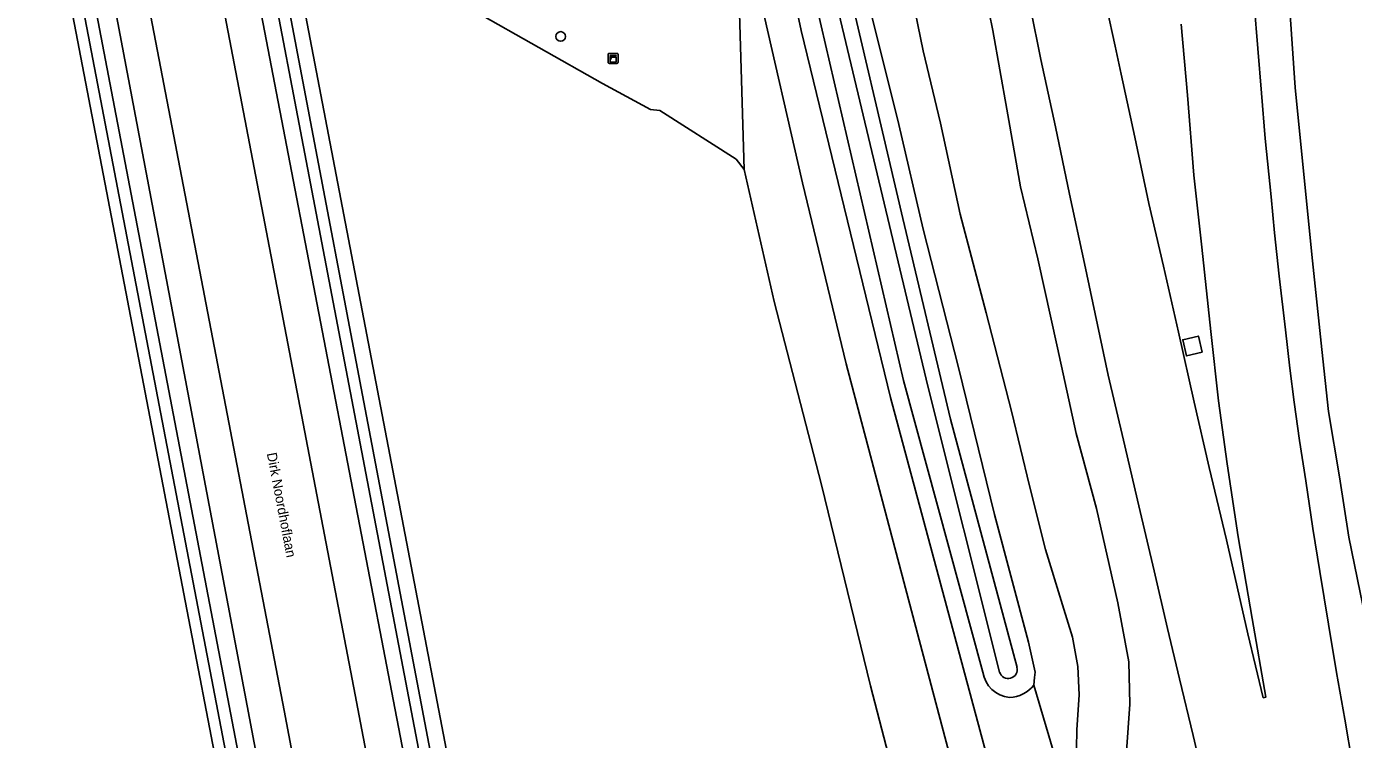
# Model space of a CAD drawing. Extents: x 155209 to 156748, y 385356 to 388487.
# Drawn here: x 155983.7 to 156118, y 387161.6 to 387233.8 of the extents above; entities that cross this region are included whole.
import ezdxf

# ---------------------------------------------------------------- set-up
doc = ezdxf.new("R2010")
doc.units = 0
for name, color, linetype in [('IMGEO_Berm_groen', 7, 'Continuous'), ('IMGEO_Boom', 7, 'Continuous'), ('IMGEO_Bouwland', 7, 'Continuous'), ('IMGEO_Grasland_overig', 7, 'Continuous'), ('IMGEO_Groenvoorziening', 7, 'Continuous'), ('IMGEO_Kast', 7, 'Continuous'), ('IMGEO_Oever', 7, 'Continuous'), ('IMGEO_Openbare_ruimte_label', 7, 'Continuous'), ('IMGEO_Rijbaan_autoweg', 7, 'Continuous'), ('IMGEO_Rijbaan_lokaal_gesloten', 7, 'Continuous'), ('IMGEO_Terreindeel_gesloten', 7, 'Continuous'), ('IMGEO_Waterloop', 7, 'Continuous')]:
    doc.layers.add(name, color=color, linetype=linetype)

msp = doc.modelspace()

# ---------------------------------------------------------------- linework, layer by layer
at = {"layer": 'IMGEO_Berm_groen'}
for points in [[(156124.08, 387145.73), (156119.4, 387172.12), (156119.79, 387171.29), (156118.68, 387176.53), (156117.56, 387182.12), (156116.6, 387188.23), (156115.48, 387194.83), (156114.83, 387201.12), (156113.86, 387210.09), (156112.91, 387219.48), (156112.12, 387227.62), (156111.58, 387235.49), (156111.1, 387240.26), (156110.59, 387248.51), (156110.09, 387261.29), (156109.74, 387274.5), (156109.48, 387287.23), (156109.39, 387301.2), (156109.43, 387313.84), (156109.38, 387326.21)], [(155947.88, 387283.75), (155948.71, 387282.8), (155982.58, 387264.03), (155982.51, 387264.23), (155983.11, 387265.71), (155985.52, 387266.24), (155987.41, 387263.41), (156023.19, 387074.38), (156023.15, 387072.76), (156022.07, 387071.71), (156020.54, 387071.32), (156012.96, 387067.09), (156012.12, 387066.35), (156011.18, 387065.51), (156010.73, 387065.11), (156010.1, 387065.36), (156008.59, 387064.11), (156010.29, 387063.34)], [(156025.74, 387080.22), (156009.76, 387164.56), (155992.17, 387256.24), (155990.17, 387266.67), (155989.94, 387268.35), (155987.99, 387269.6), (155983.87, 387268.2), (155983.02, 387267.92), (155974.17, 387271.92), (155969.49, 387274.19)], [(156080.41, 387238.88), (156081.52, 387233.39), (156082.94, 387225.44), (156084.32, 387217.55), (156086.06, 387210.27), (156088.06, 387201.26), (156089.96, 387192.59), (156092.02, 387185.03), (156094.18, 387175.46), (156095.27, 387169.51), (156095.39, 387165.23), (156095.04, 387160.42)], [(156107.97, 387236.09), (156108.7, 387227.03), (156109.08, 387222.45), (156109.7, 387216.55), (156110.03, 387212.91), (156110.51, 387208.51), (156111.14, 387203.11), (156111.58, 387199.2), (156112.01, 387195.76), (156112.54, 387191.91), (156113.18, 387187.81), (156113.92, 387182.98), (156114.61, 387178.63), (156115.49, 387173.3), (156116.31, 387168.41), (156117.14, 387163.7), (156117.92, 387159.1)], [(156103.18, 387156.15), (156101.8, 387162.04), (156100.4, 387167.78), (156099.19, 387172.87), (156097.83, 387178.72), (156096.29, 387185.27), (156094.75, 387191.94), (156093.18, 387198.52), (156090.8, 387209.8), (156089.28, 387216.83), (156087.85, 387223.62), (156086.37, 387230.44), (156085.32, 387235.63)], [(156093.06, 387235.66), (156093.89, 387231.81), (156094.5, 387228.98), (156095.88, 387222.59), (156097.31, 387215.88), (156098.79, 387209.53), (156100.32, 387202.86), (156101.88, 387195.79), (156103.4, 387189.18), (156105.15, 387181.86), (156107.32, 387172.34), (156108.89, 387165.86), (156109.16, 387165.93), (156107.77, 387173.87), (156106.35, 387182.15), (156105.24, 387189.55), (156104.36, 387195.91), (156103.59, 387202.91), (156102.67, 387211.47), (156101.86, 387218.76), (156101.22, 387226.85), (156100.59, 387234.04)]]:
    msp.add_lwpolyline(points, dxfattribs=at)
msp.add_lwpolyline([(156102.7, 387200.83), (156101.1, 387200.46), (156100.73, 387202.09), (156102.33, 387202.46)], close=True, dxfattribs=at)
at = {"layer": 'IMGEO_Boom'}
msp.add_circle((156037.77, 387232.78), 0.489, dxfattribs=at)
at = {"layer": 'IMGEO_Bouwland'}
for points in [[(155983.31, 387261.26), (155977.7, 387264.44), (155946.02, 387282), (155934.44, 387274.3), (155908.63, 387250), (155876.05, 387219.32), (155872.95, 387216.32), (155866.82, 387210.39), (155866.68, 387210.25), (155829.99, 387175.53), (155824.39, 387170.24), (155820.32, 387166.38), (155820.46, 387166.24), (155817.28, 387163.02), (155817.14, 387163.16), (155808.2, 387155.21), (155805.58, 387152.26), (155802.15, 387149.1), (155805.27, 387147.74), (155854.95, 387128.34), (156000, 387072.11), (156012.96, 387067.09), (156020.54, 387071.32), (156019.65, 387072.07)], [(156064.17, 387187.41), (156059.38, 387205.95), (156056.35, 387219.32), (156055.53, 387220.36), (156047.8, 387225.28), (156046.85, 387225.4), (156041.99, 387228.01), (156009.77, 387246.27), (156039.37, 387091.89), (156076.78, 387127.01), (156078.96, 387129.05), (156077.06, 387135.76), (156072.99, 387152.28), (156069.14, 387167.07)]]:
    msp.add_lwpolyline(points, close=True, dxfattribs=at)
msp.add_lwpolyline([(156044.88, 387040.73), (156001.43, 387266.35), (156001.45, 387267.92), (156002.48, 387269.35), (156004.33, 387269.73), (156005.47, 387268.66), (156009.77, 387246.27), (156041.99, 387228.01), (156046.85, 387225.4), (156047.8, 387225.28), (156055.53, 387220.36), (156056.35, 387219.32), (156055.84, 387236.29), (156047.02, 387279.97), (156046.87, 387280.78), (155998.24, 387271.2), (155998.01, 387270.89), (155997.11, 387269.67), (156016.95, 387166.15), (156032.7, 387083.72)], dxfattribs=at)
at = {"layer": 'IMGEO_Grasland_overig'}
for points in [[(156027.54, 387557.22), (156027.62, 387546.78), (156027.42, 387516.8), (156028.65, 387483.23), (156030.14, 387455.45), (156032.35, 387424.76), (156034.61, 387401.66), (156038.15, 387370.39), (156042.46, 387338.51), (156047.03, 387310.12), (156049.29, 387296.42), (156055.09, 387266.23), (156062.12, 387233.38), (156071.16, 387196.26), (156081.89, 387156.33), (156090.36, 387124.96), (156100.47, 387087.38), (156109.71, 387056.23), (156112.76, 387045.81), (156117.12, 387031.93)], [(156051.56, 387326.11), (156053.06, 387317.03), (156055.2, 387305.56), (156057.16, 387294.73), (156059.48, 387283.2), (156061.25, 387272.56), (156062.57, 387265.36), (156064.64, 387255.74), (156066.86, 387244.97), (156068.39, 387238.38), (156071.98, 387223.87), (156074.47, 387213.29), (156078.03, 387199.27), (156081.69, 387184.41), (156085.12, 387171.5), (156085.79, 387168.45), (156085.73, 387167.9), (156085.66, 387167.13), (156095.73, 387133.19)], [(156056.92, 387322), (156059.1, 387309.12), (156061.83, 387294.35), (156064.33, 387280.36), (156066.57, 387267.88), (156067, 387265.48), (156070.1, 387251.29), (156073.33, 387236.78), (156074.47, 387231.32), (156076.2, 387224.02), (156078.22, 387214.79), (156080.83, 387204.83), (156083.39, 387194.86), (156085.22, 387187.3), (156086.83, 387180.87), (156088.55, 387175.26), (156089.57, 387171.99), (156090.13, 387169.04), (156090.26, 387166.15), (156090, 387162.62), (156089.96, 387158.83)], [(156089.96, 387158.83), (156090, 387162.62), (156090.26, 387166.15), (156090.13, 387169.04), (156089.57, 387171.99), (156088.55, 387175.26), (156086.83, 387180.87), (156085.22, 387187.3), (156083.39, 387194.86), (156080.83, 387204.83), (156078.22, 387214.79), (156076.2, 387224.02), (156074.47, 387231.32), (156073.33, 387236.78), (156070.1, 387251.29), (156067, 387265.48), (156066.57, 387267.88), (156064.33, 387280.36), (156061.83, 387294.35), (156059.1, 387309.12), (156056.92, 387322)], [(156080.49, 387168.45), (156072.47, 387197.97), (156062.39, 387241.43), (156058.9, 387257.1), (156054.08, 387282.98), (156050.84, 387302.29), (156047.64, 387320.03)], [(156095.04, 387160.42), (156095.39, 387165.23), (156095.27, 387169.51), (156094.18, 387175.46), (156092.02, 387185.03), (156089.96, 387192.59), (156088.06, 387201.26), (156086.06, 387210.27), (156084.32, 387217.55), (156082.94, 387225.44), (156081.52, 387233.39), (156080.41, 387238.88)], [(156095.73, 387133.19), (156085.66, 387167.13)]]:
    msp.add_lwpolyline(points, dxfattribs=at)
for centre, radius, start, end in [((156083.5, 387168.93), 3.04, 189.1217, 264.4738), ((156083.09, 387169.19), 3.29, 272.035, 321.3376)]:
    msp.add_arc(centre, radius, start, end, dxfattribs=at)
at = {"layer": 'IMGEO_Groenvoorziening'}
msp.add_lwpolyline([(156109.38, 387326.21), (156109.43, 387313.84), (156109.39, 387301.2), (156109.48, 387287.23), (156109.74, 387274.5), (156110.09, 387261.29), (156110.59, 387248.51), (156111.1, 387240.26), (156111.58, 387235.49), (156112.12, 387227.62), (156112.91, 387219.48), (156113.86, 387210.09), (156114.83, 387201.12), (156115.48, 387194.83), (156116.6, 387188.23), (156117.56, 387182.12), (156118.68, 387176.53), (156119.79, 387171.29), (156120.29, 387168.65), (156121.38, 387164.83), (156122.51, 387161.99), (156123.57, 387158.75)], dxfattribs=at)
msp.add_lwpolyline([(156066.68, 387199.67), (156062.24, 387217.98), (156057.95, 387236.69), (156053.47, 387257.31), (156049.77, 387275.85), (156048.78, 387281.15), (156046.87, 387280.78), (156047.02, 387279.97), (156055.84, 387236.29), (156056.35, 387219.32), (156059.38, 387205.95), (156064.17, 387187.41), (156069.14, 387167.07), (156072.99, 387152.28), (156077.06, 387135.76), (156078.96, 387129.05), (156084.15, 387133.91), (156076.64, 387161.91)], close=True, dxfattribs=at)
at = {"layer": 'IMGEO_Kast'}
for p, q in [((156042.57, 387230.14), (156042.57, 387230.98)), ((156042.57, 387230.98), (156042.57, 387230.14)), ((156042.65, 387231.06), (156043.49, 387231.06)), ((156043.49, 387231.06), (156042.65, 387231.06)), ((156043.57, 387230.99), (156043.57, 387230.15)), ((156043.57, 387230.15), (156043.57, 387230.99)), ((156043.5, 387230.06), (156042.66, 387230.06)), ((156042.66, 387230.06), (156043.5, 387230.06))]:
    msp.add_line(p, q, dxfattribs=at)
for points in [[(156042.77, 387230.85), (156043.37, 387230.85), (156043.37, 387230.77), (156042.77, 387230.77), (156042.77, 387230.85)], [(156042.77, 387230.68), (156043.37, 387230.68), (156043.37, 387230.19), (156042.77, 387230.19), (156042.77, 387230.68)]]:
    msp.add_lwpolyline(points, dxfattribs=at)
msp.add_circle((156042.85, 387230.53), 0.0377, dxfattribs=at)
for centre, start, end in [((156042.65, 387230.99), 92.4484, 184.2845), ((156042.65, 387230.99), 92.4484, 184.2845), ((156043.49, 387230.99), 2.4484, 94.2845), ((156043.49, 387230.99), 2.4484, 94.2845), ((156042.65, 387230.14), 182.4484, 274.2845), ((156042.65, 387230.14), 182.4484, 274.2845), ((156043.49, 387230.14), 272.4484, 4.2845), ((156043.49, 387230.14), 272.4484, 4.2845)]:
    msp.add_arc(centre, 0.0779, start, end, dxfattribs=at)
at = {"layer": 'IMGEO_Oever'}
for points in [[(156047.63, 387341.22), (156051.29, 387316.99), (156055.64, 387291.24), (156060.36, 387267.05), (156065.95, 387241.84), (156072.4, 387214.36), (156077.24, 387194.04), (156083.96, 387168.94)], [(156082.2, 387168.45), (156074.93, 387197.4), (156064.5, 387241.1), (156055.96, 387282.33), (156052.8, 387300.61), (156047.25, 387331.74)], [(156085.66, 387167.13), (156085.73, 387167.9), (156085.79, 387168.45), (156085.12, 387171.5), (156081.69, 387184.41), (156078.03, 387199.27), (156074.47, 387213.29), (156071.98, 387223.87), (156068.39, 387238.38), (156066.86, 387244.97), (156064.64, 387255.74), (156062.57, 387265.36), (156061.25, 387272.56), (156059.48, 387283.2), (156057.16, 387294.73), (156055.2, 387305.56), (156053.06, 387317.03), (156051.56, 387326.11)], [(156047.64, 387320.03), (156050.84, 387302.29), (156054.08, 387282.98), (156058.9, 387257.1), (156062.39, 387241.43), (156072.47, 387197.97), (156080.49, 387168.45)]]:
    msp.add_lwpolyline(points, dxfattribs=at)
for points in [[(156001.43, 387266.35), (156044.88, 387040.73), (156045.6, 387038.35), (156046.7, 387037.25), (156048.01, 387037.48), (156049.03, 387038.45), (156049.4, 387039.61), (156040.62, 387085.43), (156039.37, 387091.89), (156009.77, 387246.27), (156005.47, 387268.66), (156004.33, 387269.73), (156002.48, 387269.35), (156001.45, 387267.92)], [(156002.8, 387268.42), (156002.71, 387268.82), (156003.86, 387269.09), (156004.03, 387268.32), (156047.43, 387040.3), (156046.43, 387040.12)], [(155982.58, 387264.03), (155983, 387262.89), (155983.31, 387261.26), (156019.65, 387072.07), (156020.54, 387071.32), (156022.07, 387071.71), (156023.15, 387072.76), (156023.19, 387074.38), (155987.41, 387263.41), (155985.52, 387266.24), (155983.11, 387265.71), (155982.51, 387264.23)], [(155984.17, 387263.08), (155983.89, 387264.11), (155984.17, 387264.17), (155983.98, 387265.13), (155984.9, 387265.42), (155985.06, 387264.36), (155985.28, 387263.86), (156021.93, 387072.6), (156022.03, 387072.16), (156020.84, 387071.88), (156020.71, 387072.48)]]:
    msp.add_lwpolyline(points, close=True, dxfattribs=at)
for centre, radius, start, end in [((156083.07, 387168.73), 0.912, 197.6383, 13.7261), ((156083.5, 387168.93), 3.04, 189.1217, 264.4738), ((156083.09, 387169.19), 3.29, 272.035, 321.3376)]:
    msp.add_arc(centre, radius, start, end, dxfattribs=at)
at = {"layer": 'IMGEO_Rijbaan_autoweg'}
for points in [[(156117.92, 387159.1), (156117.14, 387163.7), (156116.31, 387168.41), (156115.49, 387173.3), (156114.61, 387178.63), (156113.92, 387182.98), (156113.18, 387187.81), (156112.54, 387191.91), (156112.01, 387195.76), (156111.58, 387199.2), (156111.14, 387203.11), (156110.51, 387208.51), (156110.03, 387212.91), (156109.7, 387216.55), (156109.08, 387222.45), (156108.7, 387227.03), (156107.97, 387236.09)], [(156085.32, 387235.63), (156086.37, 387230.44), (156087.85, 387223.62), (156089.28, 387216.83), (156090.8, 387209.8), (156093.18, 387198.52), (156094.75, 387191.94), (156096.29, 387185.27), (156097.83, 387178.72), (156099.19, 387172.87), (156100.4, 387167.78), (156101.8, 387162.04), (156103.18, 387156.15)], [(156100.59, 387234.04), (156101.22, 387226.85), (156101.86, 387218.76), (156102.67, 387211.47), (156103.59, 387202.91), (156104.36, 387195.91), (156105.24, 387189.55), (156106.35, 387182.15), (156107.77, 387173.87), (156109.16, 387165.93), (156108.89, 387165.86), (156107.32, 387172.34), (156105.15, 387181.86), (156103.4, 387189.18), (156101.88, 387195.79), (156100.32, 387202.86), (156098.79, 387209.53), (156097.31, 387215.88), (156095.88, 387222.59), (156094.5, 387228.98), (156093.89, 387231.81), (156093.06, 387235.66)]]:
    msp.add_lwpolyline(points, dxfattribs=at)
at = {"layer": 'IMGEO_Rijbaan_lokaal_gesloten'}
for points in [[(156071.16, 387196.26), (156062.12, 387233.38), (156055.09, 387266.23), (156049.29, 387296.42), (156047.03, 387310.12), (156042.46, 387338.51), (156038.15, 387370.39), (156034.61, 387401.66), (156032.35, 387424.76), (156030.14, 387455.45), (156028.65, 387483.23), (156027.42, 387516.8), (156027.62, 387546.78), (156027.54, 387557.22)], [(156023.95, 387554.1), (156024.11, 387543.92), (156023.95, 387535.86), (156024.01, 387519.99), (156024.47, 387501.51), (156025.96, 387471.53), (156027.8, 387439.19), (156029.55, 387418.04), (156030.94, 387404.18), (156035.09, 387368.15), (156037.92, 387346.64), (156041.82, 387321.12), (156045.31, 387299.66), (156047.45, 387288.26), (156048.78, 387281.15), (156049.77, 387275.85), (156053.47, 387257.31), (156057.95, 387236.69), (156062.24, 387217.98), (156066.68, 387199.67), (156076.64, 387161.91), (156084.15, 387133.91), (156085.96, 387127.15), (156104.4, 387060.48)], [(156054.86, 386968.12), (156052.13, 386981.86), (156048.88, 386998.73), (156046, 387013.89), (156043.83, 387025.26), (156041.49, 387037.48), (156032.7, 387083.72), (156016.95, 387166.15), (155997.11, 387269.67), (155995.77, 387276.62), (155986.4, 387325.52)], [(155980.67, 387315.87), (155987.67, 387279.96), (155988.51, 387275.75), (155989.94, 387268.35), (155990.17, 387266.67), (155992.17, 387256.24), (156009.76, 387164.56), (156025.74, 387080.22)], [(156103.08, 387054.11), (156109.71, 387056.23), (156100.47, 387087.38), (156090.36, 387124.96), (156081.89, 387156.33), (156071.16, 387196.26)]]:
    msp.add_lwpolyline(points, dxfattribs=at)
at = {"layer": 'IMGEO_Terreindeel_gesloten'}
msp.add_lwpolyline([(156102.7, 387200.83), (156102.33, 387202.46), (156100.73, 387202.09), (156101.1, 387200.46)], close=True, dxfattribs=at)
at = {"layer": 'IMGEO_Waterloop'}
for points in [[(156083.96, 387168.94), (156077.24, 387194.04), (156072.4, 387214.36), (156065.95, 387241.84), (156060.36, 387267.05), (156055.64, 387291.24), (156051.29, 387316.99), (156047.63, 387341.22)], [(156047.25, 387331.74), (156052.8, 387300.61), (156055.96, 387282.33), (156064.5, 387241.1), (156074.93, 387197.4), (156082.2, 387168.45)]]:
    msp.add_lwpolyline(points, dxfattribs=at)
for points in [[(156004.03, 387268.32), (156003.86, 387269.09), (156002.71, 387268.82), (156002.8, 387268.42), (156046.43, 387040.12), (156047.43, 387040.3)], [(155984.17, 387263.08), (156020.71, 387072.48), (156020.84, 387071.88), (156022.03, 387072.16), (156021.93, 387072.6), (155985.28, 387263.86), (155985.06, 387264.36), (155984.9, 387265.42), (155983.98, 387265.13), (155984.17, 387264.17), (155983.89, 387264.11)]]:
    msp.add_lwpolyline(points, close=True, dxfattribs=at)
msp.add_arc((156083.07, 387168.73), 0.912, 197.6383, 13.7261, dxfattribs=at)

# ---------------------------------------------------------------- texts
at = {"layer": 'IMGEO_Openbare_ruimte_label'}
msp.add_text('Dirk Noordhoflaan', height=1, rotation=280.8379, dxfattribs=at).set_placement((156008.01, 387190.58))

doc.saveas('drawing.dxf')
